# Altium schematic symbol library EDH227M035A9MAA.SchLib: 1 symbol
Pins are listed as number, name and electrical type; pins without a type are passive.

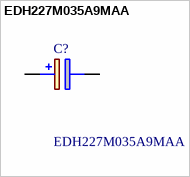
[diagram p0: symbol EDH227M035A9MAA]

## EDH227M035A9MAA
designator C?
EDH, Aluminum, Aluminum Electrolytic, 220 uF, 20%, 35 VDC, -40/+105C, 105C, -40C, 105C, 2,000 Hrs, 14 % , 0.26, 77 uA, 2, 3, 8mm, 10.2mm, 500; Manufacturer_Name: KEMET; Geometry.Height: 10.5mm
footprint CAPAE830X1050N
pins: 1 +, 2 -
